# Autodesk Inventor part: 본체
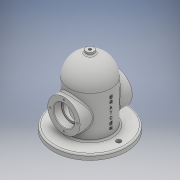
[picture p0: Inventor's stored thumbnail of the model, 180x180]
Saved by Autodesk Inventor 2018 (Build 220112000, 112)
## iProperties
Created: 2019-11
Part Number: 본체
Material: 일반
Document SubType Name: Modeling
Designer: USER
Density: 1 g/cm^3
Appearance: 기본값
Mass: 409.676 g
Surface Area: 884.221 cm^2
Volume: 409.676 cm^3
Author: USER
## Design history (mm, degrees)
sketch "스케치1"
  geometry: C1 r 70 at (0, 0); 1 further point
  constraints: 1 centre point, 1 coincident
  dimensions: "d0" = 140 diameter of C1
extrude "돌출1" new body sketch "스케치1" distance "d1" = 10; taper "d2" = 0 deg
sketch "스케치4"
  geometry: C1 r 40 at (0, 0); 1 further point
  constraints: 1 centre point, 1 coincident
  dimensions: "d5" = 80 diameter of C1
extrude "돌출2" join sketch "스케치4" distance "d6" = 80; taper "d7" = 0 deg
sketch "스케치5"
  geometry: L1 (40, 90)-(-40, 90) reference; L2 (0, 130)-(0, 0); L3 (-40, 90)-(0, 90); L4 (0, 130)-(0, 90); A1 r 40 centre (0, 90) between (0, 130) and (-40, 90)
  constraints: 8 end point, 2 perpendicular, 2 point on circle, 1 centre point, 1 midpoint, 1 vertical
revolve "회전1" sketch "스케치5" stored, may be unused: angle "d9" = 90 deg
node "작업 평면1"
sketch "스케치7"
  geometry: L1 (-70, 0)-(70, 0) reference; C1 r 31 at (0, 50); 2 further points
  constraints: 1 centre point, 1 midpoint, 1 vertical alignment
  dimensions: "d11" = 62 diameter of C1; "d12" = 50 distance from line of L1 C1.centre
extrude "돌출3" join sketch "스케치7" stored distance "d13" = 50; taper "d14" = 0 deg
sketch "스케치8"
  geometry: C1 r 31 at (0, 0) reference; C2 r 20 at (0, 0); 1 further point
  constraints: 1 centre point, 1 coincident
  dimensions: "d15" = 40 diameter of C2
extrude "돌출4" cut sketch "스케치8" distance "d16" = 15; taper "d17" = 0 deg
sketch "스케치9"
  geometry: C1 r 20 at (0, 0) reference; C2 r 16.5 at (0, 0); 1 further point
  constraints: 1 centre point, 1 coincident
  dimensions: "d18" = 33 diameter of C2
extrude "돌출5" cut sketch "스케치9" extent not by distance; stored distance "d19" = 15; taper "d20" = 0 deg
sketch "스케치13"
  geometry: C1 r 30 at (0, 0); 1 further point
  constraints: 1 centre point, 1 coincident
  dimensions: "d21" = 60 diameter of C1
extrude "돌출6" cut sketch "스케치13" distance "d22" = 90; taper "d23" = 0 deg
sketch "스케치14"
  geometry: L1 (0, 0)-(0, 140.501); L2 (30, 90)-(-30, 90) reference; L3 (-30, 90)-(0, 90); L4 (0, 90)-(0, 120); A1 r 30 centre (0, 90) between (0, 120) and (-30, 90)
  constraints: 7 end point, 3 point on circle, 2 point on line, 1 centre point, 1 collinear, 1 midpoint, 1 perpendicular, 1 vertical
revolve "회전2" sketch "스케치14" stored, may be unused: angle "d24" = 90 deg
node "작업 평면3"
sketch "스케치16"
  geometry: C1 r 40 at (0, 0) reference; C2 r 7.5 at (0, 0); 1 further point
  constraints: 1 centre point, 1 coincident
  dimensions: "d27" = 15 diameter of C2
extrude "돌출7" join sketch "스케치16" stored distance "d28" = 5; taper "d29" = 0 deg
sketch "스케치18"
  geometry: 2 further points
  constraints: 1 coincident
hole "구멍1" sketch "스케치18" at (0, 0) diameter "d30" = 5.188; stored, may be unused: countersink angle "d34" = 90 deg, drill point angle "d36" = 118 deg; dims "d31" = 40, "d32" = 4, "d33" = 2, "d35" = 42
sketch "스케치19" dims "d37" = 52
  geometry: C1 r 16.5 at (0, 0) reference; 3 further points
  constraints: 2 vertical alignment, 1 coincident, 2 other
hole "구멍2" sketch "스케치19" at (0, 26) diameter "d38" = 3.242; stored, may be unused: countersink angle "d42" = 90 deg, drill point angle "d44" = 118 deg; dims "d39" = 8, "d40" = 4, "d41" = 2, "d43" = 10
node "작업 평면4"
sketch "스케치20"
  geometry: L1 (-70, -10)-(70, -10) reference; 3 further points
  constraints: 1 midpoint, 1 vertical alignment, 1 other
  dimensions: "d48" = 50 distance from line of L1 point (0, 40)
extrude "돌출8" join sketch "스케치20" distance "d49" = 0.5; taper "d50" = 0 deg
sketch "스케치22" dims "d52" = 110
  geometry: C1 r 4.5 at (-55, 0); 2 further points
  constraints: 2 horizontal alignment, 1 centre point, 1 coincident, 2 other
  dimensions: "d54" = 9 diameter of C1
extrude "돌출9" cut sketch "스케치22" distance "d55" = 15; taper "d56" = 0 deg
fillet "모깎기2" dims "d57" = 3
chamfer "모따기1" distance "d58" = 1; stored, may be unused: second distance "d59" = 2, angle "d60" = 45 deg
fillet "모깎기3" dims "d61" = 0.3
node "솔리드1"
mirror "미러1"
mirror "미러2"
pattern_circular "원형 패턴1" dims angle "d46" = 360 deg
mirror "미러3"
mirror "미러4"
node "투영된 루프1"
other parameters: "d26" = 135
